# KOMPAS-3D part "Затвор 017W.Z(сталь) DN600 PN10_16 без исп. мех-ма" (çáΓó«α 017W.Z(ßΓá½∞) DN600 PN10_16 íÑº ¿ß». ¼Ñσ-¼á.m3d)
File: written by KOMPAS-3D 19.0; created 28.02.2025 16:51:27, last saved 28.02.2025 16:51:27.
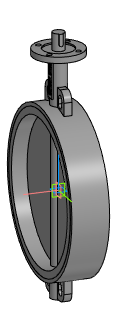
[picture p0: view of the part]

Document properties: Автор: Евгений; Полное имя файла: E:\Dendor Работа Сачек\3D для проекитирвщиков\1.5 Тип 017W.Z Сталь Затвор дисковый поворотный Межфланцевый\stp_Тип 017W.Z(сталь). Затвор без исполн. механизма\Затвор 017W.Z(сталь) DN600 PN10_16 без исп. мех-ма.m3d

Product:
- Part/product: Затвор 017W.Z(сталь) DN600 PN10_16 без исп. мех-ма

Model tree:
1. Операция без истории:1  (labels: Затвор 017W.Z(сталь) DN600 PN10_16 без исп. мех-ма)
